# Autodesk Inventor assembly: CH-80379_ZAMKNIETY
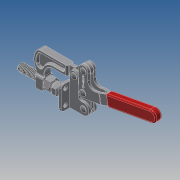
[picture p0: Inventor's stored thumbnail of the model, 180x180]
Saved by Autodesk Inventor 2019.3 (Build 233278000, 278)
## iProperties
Company: Î¢ÈíÖÐ¹ú
Created: 2012-10
Part Number: CH-80379_ZAMKNIETY
Material: Ogólny
Description: STEP AP203
Document SubType Name: Assembly
Designer: CADENGINEERING4
Sending System: SolidWorks 2010
Preprocessor: SwSTEP 2.0
Title: CH-80379.STEP
Author: Î¢ÈíÓÃ»§
Revision Number: ÈÎºÎ
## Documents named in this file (9)
- E:\SERWER_ZAPAS\F clamp\CH-80379\CH-80379_ZAMKNIETY.iam
- E:\SERWER_ZAPAS\F clamp\CH-80379\1-2-12X2 1-2.ipt
- E:\SERWER_ZAPAS\F clamp\CH-80379\80379-04 CONNECTING-PLATE.ipt
- E:\SERWER_ZAPAS\F clamp\CH-80379\80379-06_Default.ipt
- E:\SERWER_ZAPAS\F clamp\CH-80379\80379-03 HANDLE.ipt
- E:\SERWER_ZAPAS\F clamp\CH-80379\1-2 NUT.ipt
- E:\SERWER_ZAPAS\F clamp\CH-80379\80379-01 FLANGED BASE.ipt
- E:\SERWER_ZAPAS\F clamp\CH-80379\80379-02 BAR.ipt
- E:\SERWER_ZAPAS\F clamp\CH-80379\80325-05.ipt
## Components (12 placed, 12 different names)
1. 1-2-12X2 1-2_1
2. 80379-04 CONNECTING-PLATE_2
3. 80379-06_Default_3
4. 80379-03 HANDLE_4
5. 80379-06_Default_5
6. 1-2 NUT_6
7. 80379-01 FLANGED BASE_7
8. 80379-02 BAR_8
9. 80379-04 CONNECTING-PLATE_9
10. 80379-06_Default_10
11. 80379-06_Default_11
12. 80325-05_12
